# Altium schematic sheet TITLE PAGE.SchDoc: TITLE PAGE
size A; SheetNumber: 1; SheetTotal: 8
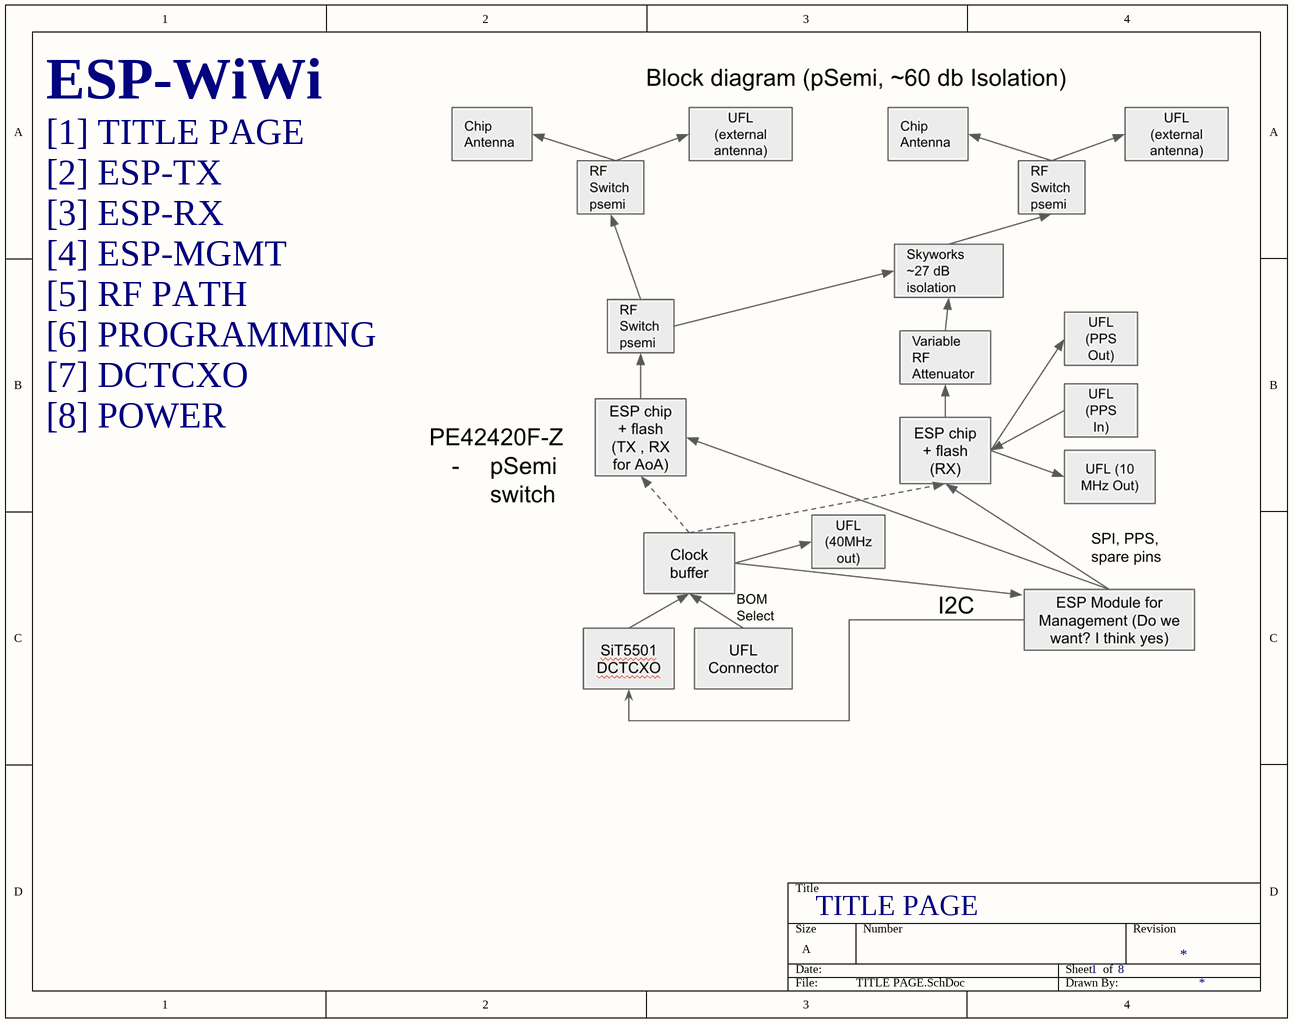
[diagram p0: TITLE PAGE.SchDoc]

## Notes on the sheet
- ESP-WiWi
- [1] TITLE PAGE
- [2] ESP-TX
- [3] ESP-RX
- [4] ESP-MGMT
- [5] RF PATH
- [6] PROGRAMMING
- [7] DCTCXO
- [8] POWER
